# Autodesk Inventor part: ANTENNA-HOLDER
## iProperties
Created: 2007-08
Part Number: ANTENNA-HOLDER
Material: ABS Plastic
Document SubType Name: Modeling
Density: 1.06 g/cm^3
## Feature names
1. Base1
